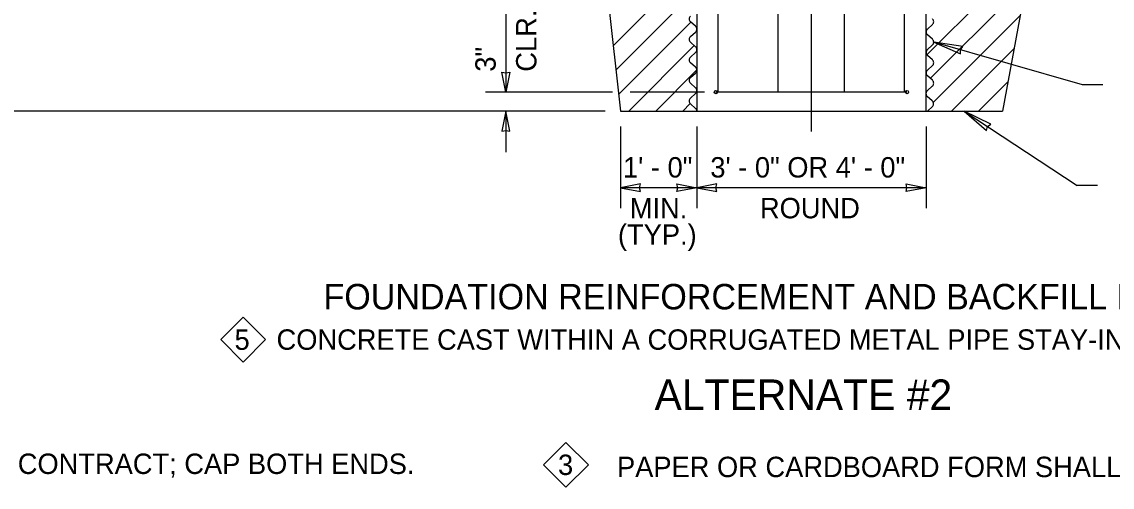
# Model space of a CAD drawing. Extents: x 99862 to 103151, y 100000 to 102076.
# Drawn here: x 101145 to 102001, y 101029 to 101394 of the extents above; entities that cross this region are included whole.
import ezdxf

# ---------------------------------------------------------------- set-up
doc = ezdxf.new("R2010")
doc.units = 0
for name, color, linetype in [('Level 13', 7, 'Continuous'), ('Level 15', 7, 'Continuous'), ('Level 17', 7, 'Continuous'), ('Level 2', 7, 'Continuous'), ('Level 20', 7, 'Continuous')]:
    doc.layers.add(name, color=color, linetype=linetype)

msp = doc.modelspace()

# ---------------------------------------------------------------- linework, layer by layer
at = {"layer": 'Level 13'}
for p, q in [((101558.72, 101828.81), (101614.81, 101323.99)), ((101691.69, 101338.99), (101691.69, 101798.99)), ((101790.85, 101338.99), (101790.85, 101798.99)), ((101837.94, 101338.99), (101837.94, 101798.99)), ((101976.23, 101656.65), (101914.81, 101323.99)), ((101738.77, 101338.99), (101738.77, 101477.79)), ((101855.48, 101368.22), (101938.26, 101450.99)), ((101609.1, 101375.38), (101673.13, 101439.41)), ((101611.22, 101356.29), (101674.74, 101419.8)), ((101858.18, 101349.69), (101933.46, 101424.98)), ((101613.34, 101337.2), (101670.06, 101393.92)), ((101860.47, 101330.77), (101928.65, 101398.96)), ((101621.35, 101323.99), (101672.83, 101375.47)), ((101874.89, 101323.99), (101923.85, 101372.94)), ((101642.56, 101323.99), (101674.69, 101356.11)), ((101896.11, 101323.99), (101919.05, 101346.93)), ((101839.81, 101338.99), (101689.81, 101338.99)), ((101614.81, 101323.99), (101674.81, 101323.99)), ((101663.77, 101323.99), (101669.72, 101329.93)), ((101855.94, 101323.99), (101914.81, 101323.99))]:
    msp.add_line(p, q, dxfattribs=at)
for centre in [(101689.81, 101338.99), (101839.81, 101338.99)]:
    msp.add_circle(centre, 1.25, dxfattribs=at)
at = {"layer": 'Level 15'}
for p, q in [((101764.81, 101307.99), (101764.81, 102030.59)), ((101524.94, 101402.96), (101524.94, 101338.99)), ((101977.65, 101344.65), (101860.81, 101378.09)), ((101993.65, 101344.65), (101977.65, 101344.65)), ((101608.74, 101338.99), (101508.94, 101338.99)), ((101680.82, 101338.99), (101622.6, 101338.99)), ((101602.81, 101323.99), (101102.68, 101323.99)), ((101524.94, 101323.99), (101524.94, 101291.99)), ((101884.86, 101323.99), (101973.35, 101265.84)), ((101614.81, 101311.99), (101614.81, 101247.99)), ((101674.81, 101311.99), (101674.81, 101247.99)), ((101854.81, 101311.99), (101854.81, 101247.99)), ((101674.81, 101263.99), (101614.81, 101263.99)), ((101854.81, 101263.99), (101674.81, 101263.99)), ((101989.35, 101265.84), (101973.35, 101265.84))]:
    msp.add_line(p, q, dxfattribs=at)
for points in [[(101860.81, 101378.09), (101881.94, 101368.94), (101881.74, 101372.1), (101883.58, 101374.68)], [(101524.94, 101338.99), (101521.86, 101354.71), (101524.94, 101353.98), (101528.03, 101354.71)], [(101524.94, 101323.99), (101521.86, 101308.26), (101524.94, 101308.99), (101528.03, 101308.26)], [(101884.86, 101323.99), (101902.3, 101308.96), (101903.06, 101312.03), (101905.58, 101313.94)], [(101614.81, 101263.99), (101630.54, 101260.9), (101629.81, 101263.99), (101630.54, 101267.07)], [(101674.81, 101263.99), (101659.09, 101260.9), (101659.82, 101263.99), (101659.09, 101267.07)], [(101674.81, 101263.99), (101690.54, 101260.9), (101689.81, 101263.99), (101690.54, 101267.07)], [(101854.81, 101263.99), (101839.09, 101260.9), (101839.82, 101263.99), (101839.09, 101267.07)]]:
    msp.add_lwpolyline(points, close=True, dxfattribs=at)
at = {"layer": 'Level 17'}
for p, q in [((101673.8, 101390.62), (101669.83, 101394.12)), ((101855.83, 101388.46), (101859.8, 101391.96)), ((101669.83, 101382.62), (101673.8, 101386.12)), ((101669.83, 101382.62), (101673.8, 101386.12)), ((101859.8, 101380.46), (101855.83, 101383.96)), ((101673.8, 101374.62), (101669.83, 101378.12)), ((101673.8, 101374.62), (101669.83, 101378.12)), ((101855.77, 101372.21), (101859.86, 101376.01)), ((101859.86, 101376.01), (101859.8, 101375.96)), ((101669.77, 101366.38), (101673.86, 101370.18)), ((101669.77, 101366.38), (101673.86, 101370.18)), ((101669.83, 101366.43), (101669.77, 101366.38)), ((101673.86, 101370.18), (101673.8, 101370.12)), ((101855.83, 101372.26), (101855.77, 101372.21)), ((101859.8, 101364.26), (101855.83, 101367.76)), ((101673.8, 101358.43), (101669.83, 101361.93)), ((101673.8, 101358.43), (101669.83, 101361.93)), ((101855.83, 101356.26), (101859.8, 101359.76)), ((101669.83, 101350.43), (101673.8, 101353.93)), ((101669.83, 101350.43), (101673.8, 101353.93)), ((101859.8, 101348.26), (101855.83, 101351.76)), ((101673.8, 101342.43), (101669.83, 101345.93)), ((101673.8, 101342.43), (101669.83, 101345.93)), ((101855.77, 101340.02), (101859.86, 101343.82)), ((101859.86, 101343.82), (101859.8, 101343.76)), ((101669.77, 101334.18), (101673.86, 101337.98)), ((101669.77, 101334.18), (101673.86, 101337.98)), ((101669.83, 101334.24), (101669.77, 101334.18)), ((101673.86, 101337.98), (101673.8, 101337.93)), ((101859.74, 101332.02), (101855.77, 101335.52)), ((101673.8, 101326.24), (101669.83, 101329.74)), ((101673.8, 101326.24), (101669.83, 101329.74)), ((101854.81, 101323.99), (101855.94, 101323.99)), ((101855.94, 101323.99), (101859.8, 101327.57)), ((101859.8, 101327.57), (101859.74, 101327.52))]:
    msp.add_line(p, q, dxfattribs=at)
for centre, start, end in [((101671.81, 101396.37), 131.40962, 228.59038), ((101857.81, 101394.21), 311.40962, 48.59038), ((101671.81, 101388.37), 311.40962, 48.59038), ((101671.81, 101388.37), 311.40962, 48.59038), ((101857.81, 101386.21), 131.40962, 228.59038), ((101671.81, 101380.37), 131.40962, 228.59038), ((101671.81, 101380.37), 131.40962, 228.59038), ((101671.81, 101372.37), 311.40962, 48.59038), ((101671.81, 101372.37), 311.40962, 48.59038), ((101857.81, 101378.21), 311.40962, 48.59038), ((101671.81, 101364.18), 131.40962, 228.59038), ((101671.81, 101364.18), 131.40962, 228.59038), ((101857.81, 101370.01), 131.40962, 228.59038), ((101671.81, 101356.18), 311.40962, 48.59038), ((101671.81, 101356.18), 311.40962, 48.59038), ((101857.81, 101362.01), 311.40962, 48.59038), ((101671.81, 101348.18), 131.40962, 228.59038), ((101671.81, 101348.18), 131.40962, 228.59038), ((101857.81, 101354.01), 131.40962, 228.59038), ((101671.81, 101340.18), 311.40962, 48.59038), ((101671.81, 101340.18), 311.40962, 48.59038), ((101857.81, 101346.01), 311.40962, 48.59038), ((101671.81, 101331.99), 131.40962, 228.59038), ((101671.81, 101331.99), 131.40962, 228.59038), ((101857.75, 101337.77), 131.40962, 228.59038), ((101857.75, 101329.77), 311.40962, 48.59038), ((101671.81, 101323.99), 0, 48.59038), ((101671.81, 101323.99), 0, 48.59038)]:
    msp.add_arc(centre, 3, start, end, dxfattribs=at)
at = {"layer": 'Level 2'}
for p, q in [((101674.81, 101803.99), (101674.81, 101323.99)), ((101854.81, 101323.99), (101854.81, 101803.99)), ((101674.81, 101323.99), (101854.81, 101323.99))]:
    msp.add_line(p, q, dxfattribs=at)
at = {"layer": 'Level 20'}
for points in [[(101318.62, 101162.35), (101336.17, 101144.79), (101318.62, 101127.24), (101301.07, 101144.79)], [(101572.14, 101064.18), (101589.7, 101046.62), (101572.14, 101029.07), (101554.59, 101046.62)]]:
    msp.add_lwpolyline(points, close=True, dxfattribs=at)

# ---------------------------------------------------------------- texts
for s, p in [('CLR.', (101548.94, 101354.99)), ('3"', (101516.94, 101354.99))]:
    msp.add_text(s, height=16, rotation=90, dxfattribs=at).set_placement(p)
for s, height, p in [('1\' - 0"', 16, (101616.88, 101271.99)), ('3\' - 0" OR 4\' - 0"', 16, (101685.45, 101271.99)), ('MIN.', 16, (101622.2, 101239.93)), ('ROUND', 16, (101724.42, 101239.99)), ('(TYP.)', 16, (101612.93, 101219.22)), ('FOUNDATION REINFORCEMENT AND BACKFILL DETAIL', 20, (101381.73, 101168.52)), ('5', 16, (101311.93, 101136.8)), ('CONCRETE CAST WITHIN A CORRUGATED METAL PIPE STAY-IN-PLACE FORM', 16, (101344.9, 101136.86)), ('ALTERNATE #2', 24, (101641.68, 101089.57)), ('CONDUIT SIZE AND QUANTITY AS SHOWN IN THE CONTRACT; CAP BOTH ENDS.', 16, (100621.08, 101039.43)), ('3', 16, (101565.88, 101038.63)), ('PAPER OR CARDBOARD FORM SHALL NOT STAY-IN-PLACE', 16, (101612.21, 101036.96))]:
    msp.add_text(s, height=height, dxfattribs=at).set_placement(p)

doc.saveas('drawing.dxf')
